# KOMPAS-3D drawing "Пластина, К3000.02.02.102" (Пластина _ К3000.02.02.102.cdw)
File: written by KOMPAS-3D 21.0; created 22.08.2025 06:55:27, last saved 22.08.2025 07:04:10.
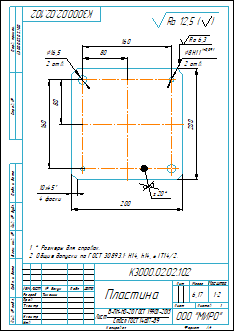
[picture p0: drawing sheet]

Sheet 1: A4, portrait

Document properties: Автор: Lutik; Полное имя файла: C:\Users\Lutik\YandexDisk\Документы\Новая папка\Бабка задняя\2D\Опора роликовая_К3000.02.02.000\Пластина _ К3000.02.02.102.cdw; Знак неуказанной шероховатости: 4; Параметр неуказанной шероховатости: Ra 12,5; Масса: 6.165676

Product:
- Part/product: Пластина  | designation К3000.02.02.102
    Материал: Лист$dБ-ПН-НО-20 ГОСТ 19903-2015;Ст3сп ГОСТ 14637-89$ (density 7850 kg/m3)
    Масса: 6.165676

Title block, sheet 1: Наименование: Пластина; designation: К3000.02.02.102; Материал: Лист Б-ПН-НО-20 ГОСТ 19903-2015 Ст3сп ГОСТ 14637-89; Масса: 6,17; Количество листов документа: 1; organisation: ООО "МИРО"; Форматы листов документа: A4; Разработал: Тимонин

Views: Вид 1, Слева
Referenced files in C:\Users\Lutik\YandexDisk\Документы\Новая папка\Бабка задняя\3D\: Пластина_7.m3d
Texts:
  Ra 6,3
  Ra 12,5
  Ra 12,5 ( )
  К3000.02.02.102 Пластина
Dimensions and other numbers on the sheet: 10; 4 фаски; 200; 80; 160; 16,5; 2 отв.; 8; 1:2; 1; 6,17

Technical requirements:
  * Размеры для справок.
  Общие допуски по ГОСТ 30893.1: Н14, h14, ± IT14/2.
